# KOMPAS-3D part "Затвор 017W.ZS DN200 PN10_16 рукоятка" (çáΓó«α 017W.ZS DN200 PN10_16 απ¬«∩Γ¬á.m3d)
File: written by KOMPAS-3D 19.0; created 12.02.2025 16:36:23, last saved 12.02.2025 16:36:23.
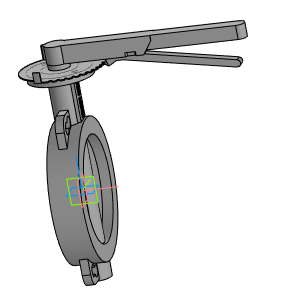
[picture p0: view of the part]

Document properties: Автор: Евгений; Полное имя файла: Затвор 017W.ZS DN200 PN10_16 рукоятка.a3d

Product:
- Part/product: Затвор 017W.ZS DN200 PN10_16 рукоятка
    Масса: 25.841

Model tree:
1. Операция без истории:1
